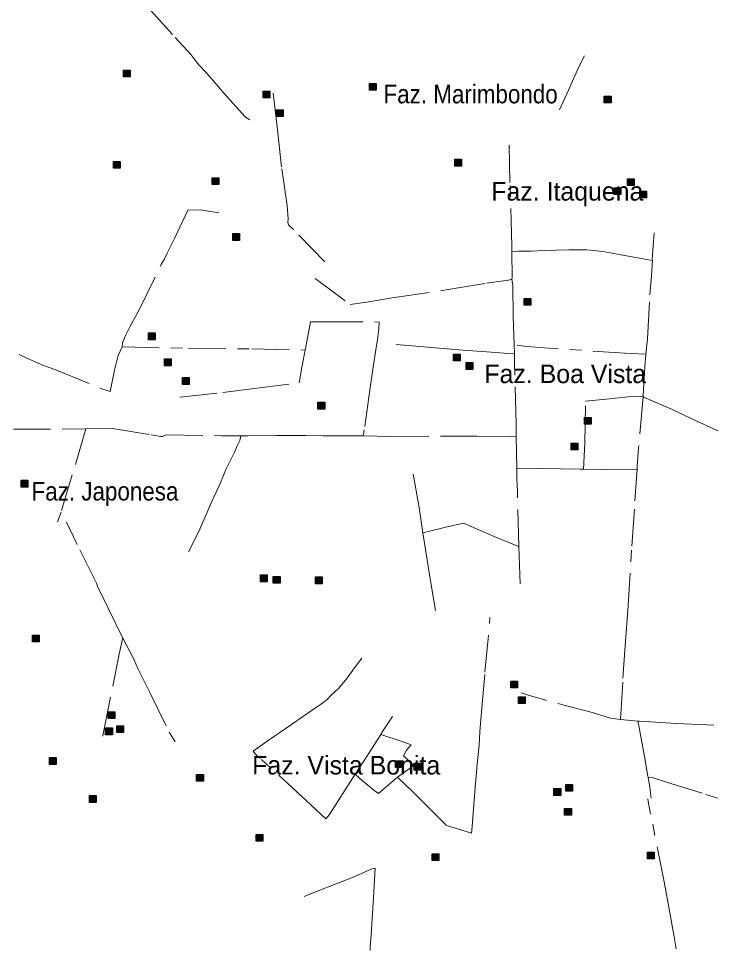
# Model space of a CAD drawing. Extents: x 393.5 to 446.9, y 8064.8 to 8120.4.
# Drawn here: x 400 to 405.95, y 8064.88 to 8072.89 of the extents above; entities that cross this region are included whole.
import ezdxf

# ---------------------------------------------------------------- set-up
doc = ezdxf.new("R2010")
doc.units = 0
doc.header["$LTSCALE"] = 0.064
doc.linetypes.add('DOT_DASHED', pattern=[7.7, 5, -1.2, 0.3, -1.2])
doc.layers.add('2', color=7, linetype='Continuous', lineweight=25)
doc.layers.add('22', color=7, linetype='DOT_DASHED', lineweight=13)
doc.layers.add('61', color=7, linetype='Continuous')

msp = doc.modelspace()

# ---------------------------------------------------------------- hatches: boundary and pattern name
at = {"layer": '2'}
for points in [[(400.9021, 8072.4522), (400.9601, 8072.4522), (400.9601, 8072.3942), (400.9021, 8072.3942)], [(403.0194, 8072.3368), (403.0774, 8072.3368), (403.0774, 8072.2788), (403.0194, 8072.2788)], [(402.1048, 8072.2708), (402.1628, 8072.2708), (402.1628, 8072.2128), (402.1048, 8072.2128)], [(405.0383, 8072.2276), (405.0963, 8072.2276), (405.0963, 8072.1696), (405.0383, 8072.1696)], [(402.22, 8072.1107), (402.278, 8072.1107), (402.278, 8072.0527), (402.22, 8072.0527)], [(400.8163, 8071.6662), (400.8743, 8071.6662), (400.8743, 8071.6082), (400.8163, 8071.6082)], [(403.7519, 8071.6848), (403.8099, 8071.6848), (403.8099, 8071.6268), (403.7519, 8071.6268)], [(401.665, 8071.5261), (401.723, 8071.5261), (401.723, 8071.4681), (401.665, 8071.4681)], [(405.2379, 8071.5158), (405.2959, 8071.5158), (405.2959, 8071.4578), (405.2379, 8071.4578)], [(405.1213, 8071.4389), (405.1793, 8071.4389), (405.1793, 8071.3809), (405.1213, 8071.3809)], [(405.3431, 8071.4105), (405.4011, 8071.4105), (405.4011, 8071.3525), (405.3431, 8071.3525)], [(401.843, 8071.0452), (401.901, 8071.0452), (401.901, 8070.9872), (401.843, 8070.9872)], [(404.3495, 8070.4861), (404.4075, 8070.4861), (404.4075, 8070.4281), (404.3495, 8070.4281)], [(401.1173, 8070.19), (401.1753, 8070.19), (401.1753, 8070.132), (401.1173, 8070.132)], [(401.2569, 8069.9665), (401.3149, 8069.9665), (401.3149, 8069.9085), (401.2569, 8069.9085)], [(403.7422, 8070.0085), (403.8002, 8070.0085), (403.8002, 8069.9505), (403.7422, 8069.9505)], [(403.8491, 8069.9352), (403.9071, 8069.9352), (403.9071, 8069.8772), (403.8491, 8069.8772)], [(401.4105, 8069.8059), (401.4685, 8069.8059), (401.4685, 8069.7479), (401.4105, 8069.7479)], [(402.5762, 8069.5935), (402.6342, 8069.5935), (402.6342, 8069.5355), (402.5762, 8069.5355)], [(404.8669, 8069.4621), (404.9249, 8069.4621), (404.9249, 8069.4041), (404.8669, 8069.4041)], [(404.7523, 8069.2417), (404.8103, 8069.2417), (404.8103, 8069.1837), (404.7523, 8069.1837)], [(400.0224, 8068.9222), (400.0804, 8068.9222), (400.0804, 8068.8642), (400.0224, 8068.8642)], [(402.0808, 8068.108), (402.1388, 8068.108), (402.1388, 8068.05), (402.0808, 8068.05)], [(402.1919, 8068.096), (402.2499, 8068.096), (402.2499, 8068.038), (402.1919, 8068.038)], [(402.5539, 8068.0905), (402.6119, 8068.0905), (402.6119, 8068.0325), (402.5539, 8068.0325)], [(400.1213, 8067.5904), (400.1793, 8067.5904), (400.1793, 8067.5324), (400.1213, 8067.5324)], [(404.2335, 8067.1951), (404.2915, 8067.1951), (404.2915, 8067.1371), (404.2335, 8067.1371)], [(404.2998, 8067.0586), (404.3578, 8067.0586), (404.3578, 8067.0006), (404.2998, 8067.0006)], [(400.7708, 8066.9301), (400.8288, 8066.9301), (400.8288, 8066.8721), (400.7708, 8066.8721)], [(400.7496, 8066.791), (400.8076, 8066.791), (400.8076, 8066.733), (400.7496, 8066.733)], [(400.8461, 8066.8093), (400.9041, 8066.8093), (400.9041, 8066.7513), (400.8461, 8066.7513)], [(400.2665, 8066.5362), (400.3245, 8066.5362), (400.3245, 8066.4782), (400.2665, 8066.4782)], [(403.2434, 8066.5077), (403.3014, 8066.5077), (403.3014, 8066.4497), (403.2434, 8066.4497)], [(403.4031, 8066.4874), (403.4611, 8066.4874), (403.4611, 8066.4294), (403.4031, 8066.4294)], [(401.5322, 8066.3908), (401.5902, 8066.3908), (401.5902, 8066.3328), (401.5322, 8066.3328)], [(404.7065, 8066.3045), (404.7645, 8066.3045), (404.7645, 8066.2465), (404.7065, 8066.2465)], [(400.611, 8066.2087), (400.669, 8066.2087), (400.669, 8066.1507), (400.611, 8066.1507)], [(404.6059, 8066.2695), (404.6639, 8066.2695), (404.6639, 8066.2115), (404.6059, 8066.2115)], [(404.6972, 8066.0989), (404.7552, 8066.0989), (404.7552, 8066.0409), (404.6972, 8066.0409)], [(402.0437, 8065.875), (402.1017, 8065.875), (402.1017, 8065.817), (402.0437, 8065.817)], [(405.4089, 8065.7232), (405.4669, 8065.7232), (405.4669, 8065.6652), (405.4089, 8065.6652)], [(403.5588, 8065.7081), (403.6168, 8065.7081), (403.6168, 8065.6501), (403.5588, 8065.6501)]]:
    msp.add_hatch(color=256, dxfattribs=at).paths.add_polyline_path(points)

# ---------------------------------------------------------------- linework, layer by layer
for points in [[(400.9021, 8072.4522), (400.9601, 8072.4522), (400.9601, 8072.3942), (400.9021, 8072.3942)], [(403.0194, 8072.3368), (403.0774, 8072.3368), (403.0774, 8072.2788), (403.0194, 8072.2788)], [(402.1048, 8072.2708), (402.1628, 8072.2708), (402.1628, 8072.2128), (402.1048, 8072.2128)], [(405.0383, 8072.2276), (405.0963, 8072.2276), (405.0963, 8072.1696), (405.0383, 8072.1696)], [(402.22, 8072.1107), (402.278, 8072.1107), (402.278, 8072.0527), (402.22, 8072.0527)], [(400.8163, 8071.6662), (400.8743, 8071.6662), (400.8743, 8071.6082), (400.8163, 8071.6082)], [(403.7519, 8071.6848), (403.8099, 8071.6848), (403.8099, 8071.6268), (403.7519, 8071.6268)], [(401.665, 8071.5261), (401.723, 8071.5261), (401.723, 8071.4681), (401.665, 8071.4681)], [(405.2379, 8071.5158), (405.2959, 8071.5158), (405.2959, 8071.4578), (405.2379, 8071.4578)], [(405.1213, 8071.4389), (405.1793, 8071.4389), (405.1793, 8071.3809), (405.1213, 8071.3809)], [(405.3431, 8071.4105), (405.4011, 8071.4105), (405.4011, 8071.3525), (405.3431, 8071.3525)], [(401.843, 8071.0452), (401.901, 8071.0452), (401.901, 8070.9872), (401.843, 8070.9872)], [(404.3495, 8070.4861), (404.4075, 8070.4861), (404.4075, 8070.4281), (404.3495, 8070.4281)], [(401.1173, 8070.19), (401.1753, 8070.19), (401.1753, 8070.132), (401.1173, 8070.132)], [(401.2569, 8069.9665), (401.3149, 8069.9665), (401.3149, 8069.9085), (401.2569, 8069.9085)], [(403.7422, 8070.0085), (403.8002, 8070.0085), (403.8002, 8069.9505), (403.7422, 8069.9505)], [(403.8491, 8069.9352), (403.9071, 8069.9352), (403.9071, 8069.8772), (403.8491, 8069.8772)], [(401.4105, 8069.8059), (401.4685, 8069.8059), (401.4685, 8069.7479), (401.4105, 8069.7479)], [(402.5762, 8069.5935), (402.6342, 8069.5935), (402.6342, 8069.5355), (402.5762, 8069.5355)], [(404.8669, 8069.4621), (404.9249, 8069.4621), (404.9249, 8069.4041), (404.8669, 8069.4041)], [(404.7523, 8069.2417), (404.8103, 8069.2417), (404.8103, 8069.1837), (404.7523, 8069.1837)], [(400.0224, 8068.9222), (400.0804, 8068.9222), (400.0804, 8068.8642), (400.0224, 8068.8642)], [(402.0808, 8068.108), (402.1388, 8068.108), (402.1388, 8068.05), (402.0808, 8068.05)], [(402.1919, 8068.096), (402.2499, 8068.096), (402.2499, 8068.038), (402.1919, 8068.038)], [(402.5539, 8068.0905), (402.6119, 8068.0905), (402.6119, 8068.0325), (402.5539, 8068.0325)], [(400.1213, 8067.5904), (400.1793, 8067.5904), (400.1793, 8067.5324), (400.1213, 8067.5324)], [(404.2335, 8067.1951), (404.2915, 8067.1951), (404.2915, 8067.1371), (404.2335, 8067.1371)], [(404.2998, 8067.0586), (404.3578, 8067.0586), (404.3578, 8067.0006), (404.2998, 8067.0006)], [(400.7708, 8066.9301), (400.8288, 8066.9301), (400.8288, 8066.8721), (400.7708, 8066.8721)], [(400.7496, 8066.791), (400.8076, 8066.791), (400.8076, 8066.733), (400.7496, 8066.733)], [(400.8461, 8066.8093), (400.9041, 8066.8093), (400.9041, 8066.7513), (400.8461, 8066.7513)], [(400.2665, 8066.5362), (400.3245, 8066.5362), (400.3245, 8066.4782), (400.2665, 8066.4782)], [(403.2434, 8066.5077), (403.3014, 8066.5077), (403.3014, 8066.4497), (403.2434, 8066.4497)], [(403.4031, 8066.4874), (403.4611, 8066.4874), (403.4611, 8066.4294), (403.4031, 8066.4294)], [(401.5322, 8066.3908), (401.5902, 8066.3908), (401.5902, 8066.3328), (401.5322, 8066.3328)], [(404.7065, 8066.3045), (404.7645, 8066.3045), (404.7645, 8066.2465), (404.7065, 8066.2465)], [(400.611, 8066.2087), (400.669, 8066.2087), (400.669, 8066.1507), (400.611, 8066.1507)], [(404.6059, 8066.2695), (404.6639, 8066.2695), (404.6639, 8066.2115), (404.6059, 8066.2115)], [(404.6972, 8066.0989), (404.7552, 8066.0989), (404.7552, 8066.0409), (404.6972, 8066.0409)], [(402.0437, 8065.875), (402.1017, 8065.875), (402.1017, 8065.817), (402.0437, 8065.817)], [(405.4089, 8065.7232), (405.4669, 8065.7232), (405.4669, 8065.6652), (405.4089, 8065.6652)], [(403.5588, 8065.7081), (403.6168, 8065.7081), (403.6168, 8065.6501), (403.5588, 8065.6501)]]:
    msp.add_lwpolyline(points, close=True, dxfattribs=at)
at = {"layer": '22'}
for p, q in [((405.4533, 8070.8143), (405.4491, 8070.815)), ((401.2668, 8069.3127), (401.2669, 8069.3127)), ((404.3046, 8068.3513), (404.3161, 8067.983)), ((405.1791, 8066.8655), (405.3278, 8066.8507)), ((405.3278, 8066.8507), (405.329, 8066.8506)), ((402.8888, 8066.3849), (402.8949, 8066.3942))]:
    msp.add_line(p, q, dxfattribs=at)
for points in [[(400.9678, 8073.1379), (401.0131, 8073.0964), (401.1088, 8072.9953), (401.3483, 8072.7336), (401.4845, 8072.5847), (401.5284, 8072.5274)], [(404.6528, 8072.1096), (404.7311, 8072.28), (404.8089, 8072.4553), (404.8564, 8072.5538), (404.8683, 8072.5743)], [(401.5284, 8072.5274), (401.55, 8072.4964), (401.6107, 8072.4338), (401.792, 8072.226), (401.9513, 8072.0513), (401.9881, 8072.0237)], [(402.3198, 8071.1734), (402.312, 8071.2869), (402.2618, 8071.6199), (402.2283, 8071.9371), (402.1828, 8072.3252)], [(404.2444, 8070.8913), (404.2435, 8070.9401), (404.2269, 8071.4853), (404.2187, 8071.8498)], [(401.2751, 8070.8701), (401.3414, 8071.004), (401.4574, 8071.2455), (401.5652, 8071.2499), (401.7241, 8071.2237)], [(402.6345, 8070.8034), (402.3655, 8071.0793), (402.3231, 8071.1198), (402.3176, 8071.1419), (402.3198, 8071.1734)], [(405.4681, 8071.0518), (405.4515, 8070.8217), (405.4533, 8070.8143)], [(400.891, 8070.0717), (400.8954, 8070.1057), (400.9245, 8070.1742), (400.958, 8070.2424), (401.034, 8070.3839), (401.2274, 8070.7789), (401.2537, 8070.8211), (401.2751, 8070.8701)], [(404.2445, 8070.8886), (404.2448, 8070.6658), (404.2433, 8070.6558), (404.2429, 8070.6529)], [(404.5227, 8070.899), (404.4091, 8070.895), (404.2967, 8070.8932), (404.2445, 8070.8886), (404.2444, 8070.8913)], [(405.4491, 8070.815), (405.387, 8070.8253), (405.1824, 8070.8622), (405.0258, 8070.8898), (404.8894, 8070.9064), (404.7328, 8070.9064), (404.5227, 8070.899)], [(405.3971, 8070.0079), (405.4099, 8070.1397), (405.4291, 8070.5179), (405.444, 8070.6823), (405.4533, 8070.8143)], [(402.5532, 8070.6593), (402.8517, 8070.4338), (402.9936, 8070.4541), (403.2147, 8070.4927), (403.6966, 8070.5628), (404.0255, 8070.6179), (404.2153, 8070.6455), (404.2429, 8070.6529)], [(404.265, 8070.0108), (404.2556, 8070.3348), (404.2521, 8070.5995), (404.2429, 8070.6529)], [(402.4655, 8070.0436), (402.4705, 8070.0712), (402.5123, 8070.2864), (402.644, 8070.2864), (403.0615, 8070.2864), (403.1037, 8070.2839), (403.0988, 8070.2243), (403.0867, 8070.1328)], [(403.0867, 8070.1328), (403.0628, 8069.9741), (403.0218, 8069.7016), (402.9745, 8069.3563), (402.9649, 8069.3036)], [(400.0068, 8070.0042), (400.0724, 8069.9736), (400.2167, 8069.911), (400.3131, 8069.8749), (400.7091, 8069.7132), (400.7878, 8069.6873), (400.827, 8069.8705), (400.8575, 8069.9965), (400.891, 8070.0717)], [(400.891, 8070.0717), (401.4632, 8070.0573), (402.0078, 8070.0529), (402.4653, 8070.0434), (402.4655, 8070.0434)], [(403.249, 8070.0902), (403.5547, 8070.0654), (403.7858, 8070.0455), (404.107, 8070.0213), (404.1779, 8070.0172), (404.265, 8070.0108)], [(405.3971, 8070.0079), (405.2602, 8070.0124), (404.5254, 8070.0623), (404.3689, 8070.0747), (404.2893, 8070.0847)], [(401.3892, 8069.6382), (401.758, 8069.6771), (402.007, 8069.7087), (402.4143, 8069.7597), (402.4402, 8069.9115), (402.4655, 8070.0434), (402.4655, 8070.0436)], [(404.2812, 8069.3006), (404.2795, 8069.4075), (404.2675, 8069.9228), (404.265, 8070.0108)], [(405.3723, 8069.6491), (405.3866, 8069.8984), (405.3971, 8070.0079)], [(404.8586, 8069.0179), (404.8721, 8069.2444), (404.8771, 8069.6044), (405.0834, 8069.6243), (405.2996, 8069.6467), (405.3691, 8069.6419), (405.3719, 8069.6417)], [(405.3719, 8069.6417), (405.372, 8069.6442), (405.3723, 8069.6491)], [(405.3719, 8069.6417), (405.3339, 8069.1991), (405.3209, 8069.0478), (405.3209, 8069.0153)], [(405.3719, 8069.6417), (405.4554, 8069.6033), (405.6113, 8069.5378), (405.7855, 8069.4538), (406.0336, 8069.3389), (406.1558, 8069.2823), (406.3561, 8069.1991), (406.365, 8069.2026), (406.3543, 8069.3372), (406.7496, 8069.346), (406.8398, 8069.3465)], [(399.9561, 8069.3616), (400.3747, 8069.3621), (400.5809, 8069.3653)], [(400.5809, 8069.3653), (400.4634, 8068.9699), (400.3669, 8068.6489), (400.3356, 8068.5663)], [(400.5809, 8069.3653), (400.8092, 8069.369), (401.1426, 8069.3136), (401.2239, 8069.2982), (401.2391, 8069.2983), (401.2668, 8069.3127)], [(401.2669, 8069.3127), (401.7535, 8069.3056), (401.9126, 8069.3056)], [(401.8818, 8069.2193), (401.904, 8069.2659), (401.9117, 8069.3013), (401.9126, 8069.3056)], [(402.4699, 8069.3083), (402.2199, 8069.3079), (401.9749, 8069.3056), (401.9126, 8069.3056)], [(402.9649, 8069.3036), (402.8188, 8069.3041), (402.6203, 8069.3056), (402.4699, 8069.3083)], [(402.9649, 8069.3036), (403.2095, 8069.3), (403.6726, 8069.3022), (403.7548, 8069.3022), (403.942, 8069.3015)], [(403.942, 8069.3015), (404.2377, 8069.2958), (404.2812, 8069.3006)], [(404.2857, 8069.0276), (404.2812, 8069.298), (404.2812, 8069.3006)], [(401.4634, 8068.3072), (401.5511, 8068.4813), (401.6479, 8068.7077), (401.7353, 8068.8943), (401.7872, 8069.0205), (401.859, 8069.1639), (401.8818, 8069.2193)], [(404.2857, 8069.0276), (404.5012, 8069.0232), (404.8269, 8069.0185), (404.8586, 8069.0179)], [(404.3046, 8068.3513), (404.2915, 8068.8299), (404.2873, 8068.9338), (404.2857, 8069.0276)], [(404.8586, 8069.0179), (405.1738, 8069.0115), (405.3145, 8069.0151), (405.3209, 8069.0153)], [(405.1791, 8066.8655), (405.1993, 8067.2184), (405.2215, 8067.5395), (405.2421, 8067.8026), (405.2754, 8068.3553), (405.3019, 8068.7454), (405.3144, 8068.9418), (405.3209, 8069.0153)], [(403.3958, 8068.9741), (403.4423, 8068.7043), (403.4781, 8068.4694)], [(400.6707, 8068.0358), (400.5053, 8068.3709), (400.4141, 8068.563)], [(403.4781, 8068.4694), (403.6753, 8068.5196), (403.8284, 8068.554), (404.0903, 8068.4389), (404.2815, 8068.3599), (404.3046, 8068.3513)], [(403.4781, 8068.4694), (403.508, 8068.2729), (403.5478, 8068.0402), (403.5854, 8067.8015)], [(400.8967, 8067.5642), (400.7689, 8067.8291), (400.6825, 8068.0019), (400.6707, 8068.0358)], [(403.9681, 8066.7586), (403.9825, 8066.933), (404.0124, 8067.272), (404.0554, 8067.7417)], [(400.7262, 8066.7201), (400.7289, 8066.7418), (400.8112, 8067.1511), (400.8673, 8067.4276), (400.8952, 8067.5572), (400.8967, 8067.5642)], [(400.8967, 8067.5642), (400.9882, 8067.3895), (401.0291, 8067.2958)], [(402.6859, 8067.0716), (402.7551, 8067.1346), (402.8244, 8067.2176), (402.8913, 8067.3076), (402.9525, 8067.3929)], [(401.0291, 8067.2958), (401.13, 8067.0975), (401.2977, 8066.7554), (401.3467, 8066.6708)], [(405.1791, 8066.8655), (405.0909, 8066.8742), (404.9468, 8066.9206), (404.5254, 8067.0326), (404.3753, 8067.0772), (404.3222, 8067.0931)], [(402.8109, 8066.2597), (402.7501, 8066.165), (402.6765, 8066.0464), (402.6448, 8066.008), (402.4743, 8066.1683), (402.0799, 8066.529), (402.0395, 8066.5659), (402.0199, 8066.5924), (402.1399, 8066.6778), (402.4054, 8066.8612), (402.5647, 8066.9708), (402.598, 8066.9919), (402.6548, 8067.0353), (402.6859, 8067.0716)], [(403.2159, 8066.8907), (403.1357, 8066.7704), (403.1156, 8066.7354)], [(405.4141, 8066.3756), (405.3861, 8066.5278), (405.3394, 8066.7959), (405.3278, 8066.8507)], [(405.329, 8066.8506), (405.3411, 8066.8494), (405.6618, 8066.8299), (406.1253, 8066.807), (406.5277, 8066.7794), (406.9287, 8066.7517), (406.9975, 8066.7493), (407.0004, 8066.7492)], [(403.2603, 8066.3668), (403.3976, 8066.2347), (403.5405, 8066.0919), (403.6828, 8065.9516), (403.7664, 8065.9248), (403.8951, 8065.8848), (403.9017, 8065.9415), (403.9043, 8065.9835), (403.9268, 8066.28), (403.9452, 8066.4805), (403.9619, 8066.6432), (403.9681, 8066.7586)], [(402.8949, 8066.3942), (403.0153, 8066.5767), (403.1156, 8066.7354)], [(403.3936, 8066.4742), (403.3413, 8066.5249), (403.3112, 8066.5516), (403.3362, 8066.6001), (403.378, 8066.6452), (403.2928, 8066.6769), (403.1257, 8066.732), (403.1161, 8066.7352), (403.1156, 8066.7354)], [(403.2603, 8066.3668), (403.3797, 8066.4538), (403.3964, 8066.4689), (403.3936, 8066.4742)], [(402.8888, 8066.3849), (402.8562, 8066.3312), (402.8109, 8066.2597)], [(403.2603, 8066.3668), (403.1815, 8066.3016), (403.0974, 8066.2266), (403.056, 8066.2566), (402.9368, 8066.3553), (402.8949, 8066.3942)], [(405.4163, 8066.3635), (405.4147, 8066.3721), (405.4141, 8066.3756)], [(405.4163, 8066.3635), (405.4411, 8066.3668), (405.5742, 8066.3259), (405.9114, 8066.2196), (406.1078, 8066.1571), (406.1927, 8066.1425)], [(405.4163, 8066.3635), (405.4274, 8066.3025), (405.4404, 8066.1878)], [(405.6576, 8064.8899), (405.638, 8064.9926), (405.5962, 8065.231), (405.5568, 8065.4538), (405.4371, 8066.0511), (405.4154, 8066.1595), (405.412, 8066.1811)], [(402.4572, 8065.3423), (402.6066, 8065.4016), (402.8727, 8065.5038), (403.0405, 8065.5795), (403.0684, 8065.5834), (403.0547, 8065.33), (403.0327, 8065.0139), (403.0241, 8064.9087), (403.0262, 8064.8775)]]:
    msp.add_lwpolyline(points, dxfattribs=at)

# ---------------------------------------------------------------- texts
at = {"layer": '61', "width": 0.9}
for s, p in [('Faz. Marimbondo', (403.1396, 8072.1661)), ('Faz. Japonesa', (400.1127, 8068.7483))]:
    msp.add_text(s, height=0.16, dxfattribs=at).set_placement(p)
at = {"layer": '61'}
for s, p in [('Faz. Itaquena', (404.0663, 8071.3291)), ('Faz. Boa Vista', (404.0071, 8069.7587)), ('Faz. Vista Bonita', (402.0098, 8066.3911))]:
    msp.add_text(s, height=0.16, dxfattribs=at).set_placement(p)

doc.saveas('drawing.dxf')
